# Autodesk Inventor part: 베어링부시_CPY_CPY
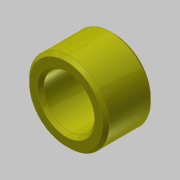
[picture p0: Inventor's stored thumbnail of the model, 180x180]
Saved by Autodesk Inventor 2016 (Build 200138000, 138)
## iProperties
Created: 2019-03
Part Number: 베어링부시_CPY_CPY
Material: 강철, 연강
Document SubType Name: Modeling
Designer: Administrator
Density: 1 g/cm^3
Appearance: 노란색
Author: mduedu
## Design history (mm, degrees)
sketch "스케치1"
  geometry: L1 (-7.5, 12.5)-(7.5, 12.5); L2 (7.5, 12.5)-(7.5, 8); L3 (7.5, 8)-(-7.5, 8); L4 (-7.5, 8)-(-7.5, 12.5); L5 (-7.5, 0)-(7.5, 0); 3 further points
  constraints: 10 end point, 2 midpoint, 2 parallel, 2 perpendicular, 2 vertical alignment, 1 coincident, 1 horizontal
  dimensions: "d0" = 16 diameter of L3 L5; "d2" = 25 diameter of L1 L5; "d3" = 15 distance of L1.start L1.end
revolve "회전1" sketch "스케치1" stored, may be unused: angle "d4" = 90 deg
chamfer "모따기1" distance "d5" = 1; stored, may be unused: second distance "d6" = 2, angle "d7" = 45 deg
chamfer "모따기2" distance "d8" = 1; stored, may be unused: second distance "d9" = 2, angle "d10" = 45 deg
node "솔리드1"
